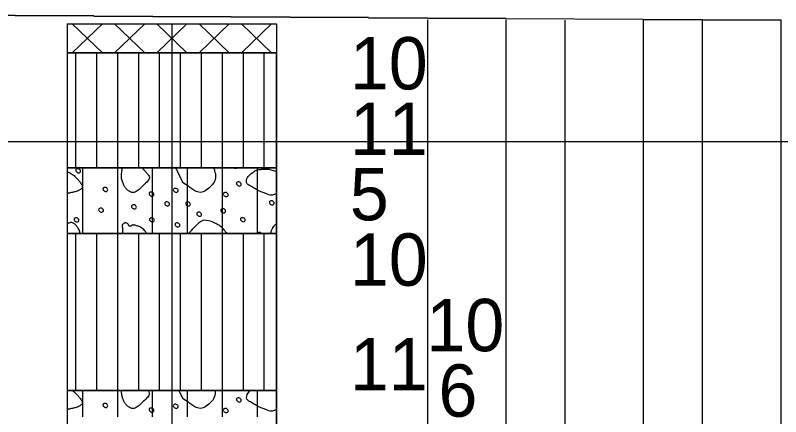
# Model space of a CAD drawing. Extents: x -2280229 to 1306, y -58886 to 440.
# Drawn here: x 316.23 to 345.48, y 91.69 to 107.02 of the extents above; entities that cross this region are included whole.
import ezdxf

# ---------------------------------------------------------------- set-up
doc = ezdxf.new("R2010")
doc.units = 0
for name, color, linetype in [('BR_P_Sub_Deep_Object', 7, 'Continuous'), ('GT_Project_Soil_Layers', 7, 'Continuous'), ('SC_Scratch2', 7, 'Continuous'), ('SH_Minor_Grid_Line', 7, 'Continuous')]:
    doc.layers.add(name, color=color, linetype=linetype)

msp = doc.modelspace()

# ---------------------------------------------------------------- linework, layer by layer
at = {"layer": 'BR_P_Sub_Deep_Object'}
for p, q in [((313.984, 107.024), (316.234, 107.024)), ((316.234, 107.011), (319.234, 107.011)), ((319.234, 106.993), (321.484, 106.993)), ((321.484, 106.979), (324.484, 106.979)), ((324.484, 106.961), (326.734, 106.961)), ((326.734, 106.948), (329.734, 106.948)), ((331.984, 106.857), (331.984, 70.692)), ((334.984, 106.898), (340.234, 106.883)), ((334.984, 106.85), (334.984, 70.692)), ((337.234, 106.845), (337.234, 70.988)), ((340.234, 106.862), (342.484, 106.862)), ((340.234, 106.839), (340.234, 70.988)), ((342.484, 106.847), (345.484, 106.847)), ((342.484, 106.833), (342.484, 71.283)), ((345.484, 106.847), (345.484, 71.283))]:
    msp.add_line(p, q, dxfattribs=at)
at = {"layer": 'GT_Project_Soil_Layers'}
for p, q in [((318.407, 105.592), (319.561, 106.693)), ((319.561, 105.592), (318.407, 106.693)), ((320.023, 105.592), (321.178, 106.693)), ((321.178, 105.592), (320.023, 106.693)), ((321.64, 105.592), (322.795, 106.693)), ((322.795, 105.592), (321.64, 106.693)), ((323.256, 105.592), (324.411, 106.693)), ((324.411, 105.592), (323.256, 106.693)), ((324.873, 105.592), (326.028, 106.693)), ((326.028, 105.592), (324.873, 106.693)), ((318.551, 103.393), (318.551, 105.593)), ((319.351, 103.393), (319.351, 105.593)), ((320.151, 103.393), (320.151, 105.593)), ((320.951, 103.393), (320.951, 105.593)), ((321.751, 103.393), (321.751, 105.593)), ((322.551, 103.393), (322.551, 105.593)), ((323.351, 103.393), (323.351, 105.593)), ((324.151, 103.393), (324.151, 105.593)), ((324.951, 103.393), (324.951, 105.593)), ((325.751, 103.393), (325.751, 105.593)), ((318.217, 105.592), (318.217, 105.592)), ((318.551, 101.193), (318.551, 103.393)), ((319.351, 101.193), (319.351, 103.393)), ((320.151, 101.193), (320.151, 103.393)), ((320.951, 101.193), (320.951, 103.393)), ((321.751, 101.193), (321.751, 103.393)), ((322.551, 101.193), (322.551, 103.393)), ((323.351, 101.193), (323.351, 103.393)), ((324.151, 101.193), (324.151, 103.393)), ((324.951, 101.193), (324.951, 103.393)), ((325.751, 101.193), (325.751, 103.393)), ((318.815, 99.943), (318.815, 101.193)), ((320.148, 99.943), (320.148, 101.193)), ((321.481, 99.943), (321.481, 101.193)), ((322.817, 99.943), (322.817, 101.193)), ((324.151, 99.943), (324.151, 101.193)), ((325.484, 99.943), (325.484, 101.193)), ((318.815, 98.693), (318.815, 99.942)), ((320.148, 98.693), (320.148, 99.942)), ((321.481, 98.693), (321.481, 99.942)), ((322.817, 98.693), (322.817, 99.942)), ((324.151, 98.693), (324.151, 99.942)), ((325.484, 98.693), (325.484, 99.942)), ((318.551, 95.693), (318.551, 98.693)), ((319.351, 95.693), (319.351, 98.693)), ((320.151, 95.693), (320.151, 98.693)), ((320.951, 95.693), (320.951, 98.693)), ((321.751, 95.693), (321.751, 98.693)), ((322.551, 95.693), (322.551, 98.693)), ((323.351, 95.693), (323.351, 98.693)), ((324.151, 95.693), (324.151, 98.693)), ((324.951, 95.693), (324.951, 98.693)), ((325.751, 95.693), (325.751, 98.693)), ((318.551, 92.693), (318.551, 95.693)), ((319.351, 92.693), (319.351, 95.693)), ((320.151, 92.693), (320.151, 95.693)), ((320.951, 92.693), (320.951, 95.693)), ((321.751, 92.693), (321.751, 95.693)), ((322.551, 92.693), (322.551, 95.693)), ((323.351, 92.693), (323.351, 95.693)), ((324.151, 92.693), (324.151, 95.693)), ((324.951, 92.693), (324.951, 95.693)), ((325.751, 92.693), (325.751, 95.693)), ((318.815, 91.693), (318.815, 92.693)), ((320.148, 91.693), (320.148, 92.693)), ((321.481, 91.693), (321.481, 92.693)), ((322.817, 91.693), (322.817, 92.693)), ((324.151, 91.693), (324.151, 92.693)), ((325.484, 91.693), (325.484, 92.693))]:
    msp.add_line(p, q, dxfattribs=at)
for points in [[(318.219, 101.193), (326.219, 101.193), (326.219, 105.593), (318.219, 105.593)], [(318.219, 98.693), (326.219, 98.693), (326.219, 101.193), (318.219, 101.193)], [(326.219, 98.693), (318.219, 98.693), (318.219, 92.693), (326.219, 92.693)], [(318.219, 90.693), (326.219, 90.693), (326.219, 92.693), (318.219, 92.693)]]:
    msp.add_lwpolyline(points, close=True, dxfattribs=at)
for points, degree in [([(318.219, 101.051), (318.246, 101.04), (318.273, 101.027), (318.3, 101.013), (318.458, 100.931), (318.564, 100.818), (318.673, 100.688), (318.743, 100.606), (318.83, 100.436), (318.738, 100.381), (318.604, 100.301), (318.452, 100.271), (318.3, 100.235), (318.273, 100.228), (318.246, 100.219), (318.219, 100.21)], 3), ([(321.088, 101.193), (321.157, 101.114), (321.226, 101.036), (321.295, 100.958), (321.423, 100.813), (321.199, 100.597), (321.037, 100.438), (320.905, 100.309), (320.707, 100.227), (320.583, 100.31), (320.487, 100.375), (320.405, 100.48), (320.357, 100.601), (320.296, 100.756), (320.288, 100.918), (320.308, 101.071), (320.314, 101.112), (320.321, 101.153), (320.331, 101.193)], 3), ([(322.643, 100.626), (322.553, 100.815), (322.462, 101.004), (322.371, 101.193)], 2), ([(323.813, 101.193), (323.83, 101.149), (323.845, 101.105), (323.856, 101.061), (323.905, 100.877), (323.856, 100.64), (323.673, 100.466), (323.489, 100.29), (323.229, 100.235), (323.055, 100.351), (322.917, 100.443), (322.78, 100.535), (322.643, 100.626)], 3), ([(324.706, 101.193), (324.705, 101.192), (324.704, 101.191), (324.703, 101.19), (324.685, 101.172), (324.667, 101.167), (324.648, 101.168), (324.631, 101.169), (324.613, 101.174), (324.596, 101.185), (324.592, 101.187), (324.588, 101.19), (324.585, 101.193)], 3), ([(325.543, 100.316), (325.414, 100.392), (325.284, 100.467), (325.155, 100.543), (325.037, 100.612), (325.1, 100.848), (325.218, 100.948), (325.357, 101.065), (325.502, 101.132), (325.656, 101.143), (325.84, 101.156), (326.034, 101.131), (326.219, 101.053)], 3), ([(326.219, 100.209), (326.121, 100.175), (326.023, 100.135), (325.931, 100.17), (325.802, 100.219), (325.672, 100.267), (325.543, 100.316)], 3), ([(322.886, 98.734), (323, 98.847), (323.113, 98.961), (323.226, 99.074), (323.387, 99.234), (323.704, 99.181), (323.906, 99.074), (324.047, 99), (324.155, 98.9), (324.263, 98.766), (324.282, 98.742), (324.301, 98.718), (324.319, 98.693)], 3), ([(318.716, 98.693), (318.695, 98.781), (318.661, 98.869), (318.592, 98.956), (318.511, 99.057), (318.382, 99.129), (318.293, 99.094), (318.27, 99.085), (318.244, 99.072), (318.219, 99.056)], 3), ([(321.246, 98.693), (321.218, 98.755), (321.173, 98.816), (321.112, 98.867), (321.037, 98.93), (320.964, 98.95), (320.882, 98.981), (320.836, 98.998), (320.79, 99.008), (320.745, 99.016), (320.702, 99.023), (320.66, 98.961), (320.618, 98.969), (320.574, 98.977), (320.557, 99.055), (320.517, 99.072), (320.481, 99.088), (320.42, 99.114), (320.39, 99.084), (320.367, 99.061), (320.345, 99.038), (320.322, 99.016)], 3), ([(320.322, 99.016), (320.325, 98.908), (320.328, 98.8), (320.331, 98.693)], 2), ([(326.219, 99.054), (326.148, 99.009), (326.078, 98.941), (326.045, 98.864), (326.028, 98.826), (326.015, 98.787), (326, 98.749)], 3), ([(322.897, 98.693), (322.893, 98.706), (322.89, 98.72), (322.886, 98.734)], 2), ([(325.481, 98.693), (325.485, 98.706), (325.495, 98.719), (325.51, 98.729), (325.526, 98.741), (325.543, 98.734), (325.56, 98.734), (325.573, 98.734), (325.59, 98.741), (325.6, 98.732), (325.615, 98.719), (325.629, 98.706), (325.644, 98.693)], 3), ([(326, 98.749), (325.995, 98.73), (325.991, 98.711), (325.987, 98.693)], 2), ([(318.414, 92.693), (318.514, 92.621), (318.592, 92.534), (318.673, 92.438), (318.743, 92.356), (318.83, 92.186), (318.738, 92.131), (318.604, 92.051), (318.452, 92.021), (318.3, 91.985), (318.273, 91.978), (318.246, 91.969), (318.219, 91.96)], 3), ([(321.307, 92.693), (321.408, 92.548), (321.193, 92.341), (321.037, 92.188), (320.905, 92.059), (320.707, 91.977), (320.583, 92.06), (320.487, 92.125), (320.405, 92.23), (320.357, 92.351), (320.313, 92.464), (320.296, 92.579), (320.298, 92.693)], 3), ([(322.643, 92.376), (322.592, 92.482), (322.542, 92.587), (322.491, 92.693)], 2), ([(323.874, 92.693), (323.879, 92.533), (323.818, 92.355), (323.673, 92.216), (323.489, 92.04), (323.229, 91.985), (323.055, 92.101), (322.917, 92.193), (322.78, 92.285), (322.643, 92.376)], 3), ([(325.543, 92.066), (325.414, 92.142), (325.284, 92.217), (325.155, 92.293), (325.039, 92.361), (325.097, 92.59), (325.212, 92.693)], 3), ([(326.219, 91.959), (326.121, 91.925), (326.023, 91.885), (325.931, 91.92), (325.802, 91.969), (325.672, 92.017), (325.543, 92.066)], 3)]:
    msp.add_open_spline(points, degree=degree, dxfattribs=at)
for points in [[(318.712, 101.116), (318.732, 101.076), (318.708, 101.028), (318.653, 101.005), (318.602, 101.023), (318.562, 101.06), (318.545, 101.1), (318.577, 101.155), (318.625, 101.16), (318.665, 101.156), (318.712, 101.116)], [(324.851, 100.615), (324.871, 100.575), (324.848, 100.526), (324.795, 100.503), (324.743, 100.52), (324.703, 100.558), (324.685, 100.598), (324.716, 100.651), (324.766, 100.658), (324.806, 100.655), (324.851, 100.615)], [(319.75, 100.401), (319.767, 100.363), (319.745, 100.315), (319.69, 100.293), (319.638, 100.31), (319.598, 100.346), (319.582, 100.386), (319.613, 100.441), (319.662, 100.446), (319.702, 100.445), (319.75, 100.401)], [(322.441, 100.368), (322.458, 100.331), (322.435, 100.283), (322.381, 100.26), (322.33, 100.276), (322.29, 100.315), (322.271, 100.355), (322.303, 100.408), (322.353, 100.415), (322.393, 100.411), (322.441, 100.368)], [(321.513, 100.226), (321.533, 100.185), (321.51, 100.136), (321.455, 100.115), (321.405, 100.131), (321.363, 100.168), (321.347, 100.208), (321.378, 100.263), (321.427, 100.268), (321.467, 100.266), (321.513, 100.226)], [(324.351, 100.206), (324.37, 100.17), (324.346, 100.121), (324.291, 100.098), (324.24, 100.116), (324.2, 100.153), (324.183, 100.193), (324.215, 100.248), (324.263, 100.253), (324.303, 100.25), (324.351, 100.206)], [(320.845, 99.736), (320.861, 99.7), (320.838, 99.651), (320.785, 99.628), (320.733, 99.645), (320.693, 99.683), (320.675, 99.723), (320.706, 99.776), (320.755, 99.783), (320.795, 99.78), (320.845, 99.736)], [(322.111, 99.85), (322.13, 99.813), (322.106, 99.765), (322.051, 99.742), (322, 99.758), (321.96, 99.797), (321.943, 99.837), (321.975, 99.89), (322.023, 99.897), (322.063, 99.893), (322.111, 99.85)], [(322.908, 99.848), (322.928, 99.808), (322.905, 99.76), (322.85, 99.736), (322.798, 99.755), (322.758, 99.791), (322.741, 99.831), (322.773, 99.886), (322.821, 99.891), (322.861, 99.888), (322.908, 99.848)], [(326.113, 99.891), (326.129, 99.852), (326.106, 99.804), (326.053, 99.782), (326.001, 99.799), (325.961, 99.836), (325.944, 99.876), (325.974, 99.931), (326.024, 99.936), (326.064, 99.934), (326.113, 99.891)], [(319.588, 99.611), (319.605, 99.573), (319.583, 99.525), (319.528, 99.501), (319.477, 99.52), (319.437, 99.556), (319.42, 99.596), (319.45, 99.651), (319.5, 99.656), (319.54, 99.653), (319.588, 99.611)], [(323.338, 99.457), (323.354, 99.419), (323.333, 99.37), (323.278, 99.347), (323.226, 99.365), (323.186, 99.402), (323.169, 99.442), (323.201, 99.497), (323.249, 99.502), (323.289, 99.499), (323.338, 99.457)], [(324.252, 99.589), (324.272, 99.549), (324.249, 99.5), (324.194, 99.477), (324.142, 99.494), (324.102, 99.532), (324.085, 99.572), (324.117, 99.625), (324.165, 99.632), (324.205, 99.629), (324.252, 99.589)], [(318.648, 99.241), (318.667, 99.202), (318.643, 99.154), (318.588, 99.131), (318.537, 99.149), (318.497, 99.186), (318.48, 99.226), (318.512, 99.281), (318.56, 99.286), (318.6, 99.282), (318.648, 99.241)], [(321.532, 99.241), (321.548, 99.202), (321.527, 99.154), (321.472, 99.131), (321.42, 99.149), (321.38, 99.186), (321.363, 99.226), (321.395, 99.281), (321.443, 99.286), (321.483, 99.282), (321.532, 99.241)], [(325.008, 99.248), (325.025, 99.21), (325.002, 99.161), (324.948, 99.138), (324.897, 99.156), (324.857, 99.193), (324.838, 99.233), (324.87, 99.288), (324.918, 99.293), (324.958, 99.29), (325.008, 99.248)], [(322.506, 99.046), (322.523, 99.009), (322.499, 98.959), (322.446, 98.937), (322.394, 98.954), (322.354, 98.991), (322.338, 99.031), (322.368, 99.086), (322.418, 99.091), (322.458, 99.089), (322.506, 99.046)], [(319.75, 92.151), (319.767, 92.113), (319.745, 92.065), (319.69, 92.043), (319.638, 92.06), (319.598, 92.096), (319.582, 92.136), (319.613, 92.191), (319.662, 92.196), (319.702, 92.195), (319.75, 92.151)], [(322.441, 92.118), (322.458, 92.081), (322.435, 92.033), (322.381, 92.01), (322.33, 92.026), (322.29, 92.065), (322.271, 92.105), (322.303, 92.158), (322.353, 92.165), (322.393, 92.161), (322.441, 92.118)], [(324.851, 92.365), (324.871, 92.325), (324.848, 92.276), (324.795, 92.253), (324.743, 92.27), (324.703, 92.308), (324.685, 92.348), (324.716, 92.401), (324.766, 92.408), (324.806, 92.405), (324.851, 92.365)], [(321.513, 91.976), (321.533, 91.935), (321.51, 91.886), (321.455, 91.865), (321.405, 91.881), (321.363, 91.918), (321.347, 91.958), (321.378, 92.013), (321.427, 92.018), (321.467, 92.016), (321.513, 91.976)], [(324.351, 91.956), (324.37, 91.92), (324.346, 91.871), (324.291, 91.848), (324.24, 91.866), (324.2, 91.903), (324.183, 91.943), (324.215, 91.998), (324.263, 92.003), (324.303, 92), (324.351, 91.956)]]:
    msp.add_spline(points, degree=3, dxfattribs=at)
at = {"layer": 'SC_Scratch2'}
for p, q in [((329.734, 106.93), (331.984, 106.93)), ((331.984, 106.916), (334.984, 106.916)), ((318.219, 106.693), (326.219, 106.693)), ((318.219, 106.693), (318.219, 60.693)), ((322.219, 106.693), (322.219, 60.693)), ((326.219, 106.693), (326.219, 60.693)), ((318.219, 105.593), (326.219, 105.593)), ((318.219, 101.193), (326.219, 101.193)), ((318.219, 98.693), (326.219, 98.693)), ((318.219, 92.693), (326.219, 92.693))]:
    msp.add_line(p, q, dxfattribs=at)
at = {"layer": 'SH_Minor_Grid_Line'}
msp.add_line((45.429, 102.208), (603.007, 102.208), dxfattribs=at)

# ---------------------------------------------------------------- texts
at = {"layer": 'SC_Scratch2'}
for s, p in [('10', (329.019, 104.193)), ('11', (329.019, 101.693)), ('5', (329.019, 99.193)), ('10', (329.019, 96.693)), ('10', (331.946, 94.193)), ('11', (329.019, 92.693)), ('6', (332.406, 91.693))]:
    msp.add_text(s, height=2, dxfattribs=at).set_placement(p)

doc.saveas('drawing.dxf')
